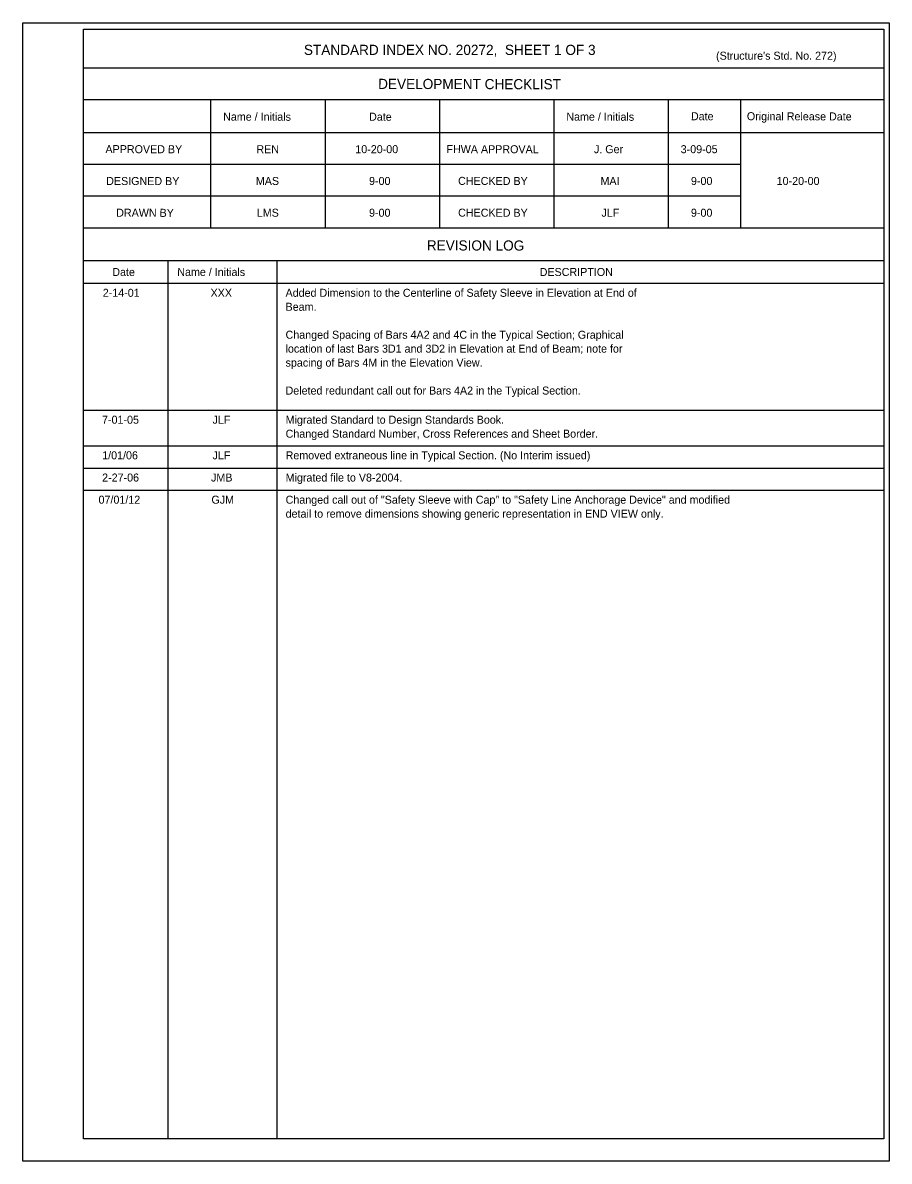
# Model space of a CAD drawing. Extents: x 120696.7 to 120732.7, y 120669.5 to 120684.8.
# Drawn here: x 120721.79 to 120732.7, y 120669.49 to 120683.83 of the extents above; entities that cross this region are included whole.
import ezdxf

# ---------------------------------------------------------------- set-up
doc = ezdxf.new("R2010")
doc.units = 0
for name, color, linetype in [('Border', 7, 'Continuous'), ('Dimension', 7, 'Continuous'), ('PlotBorder_dp', 7, 'Continuous'), ('TextStructures', 7, 'Continuous')]:
    doc.layers.add(name, color=color, linetype=linetype)

msp = doc.modelspace()

# ---------------------------------------------------------------- linework, layer by layer
at = {"layer": 'Border'}
for p, q in [((120732.633, 120683.255), (120722.559, 120683.255)), ((120732.633, 120682.855), (120722.559, 120682.855)), ((120724.159, 120682.855), (120724.159, 120681.242)), ((120725.599, 120682.855), (120725.599, 120681.242)), ((120727.039, 120682.855), (120727.039, 120681.242)), ((120728.479, 120682.855), (120728.479, 120681.242)), ((120729.919, 120682.855), (120729.919, 120681.242)), ((120730.827, 120682.855), (120730.827, 120681.242)), ((120732.633, 120682.442), (120722.559, 120682.442)), ((120730.827, 120682.042), (120722.559, 120682.042)), ((120730.827, 120681.642), (120722.559, 120681.642)), ((120732.633, 120681.242), (120722.559, 120681.242)), ((120732.633, 120680.828), (120722.559, 120680.828)), ((120723.62, 120680.828), (120723.62, 120669.774)), ((120724.991, 120680.828), (120724.991, 120669.774)), ((120732.633, 120680.546), (120722.559, 120680.546))]:
    msp.add_line(p, q, dxfattribs=at)
msp.add_lwpolyline([(120722.56, 120683.746), (120732.633, 120683.746), (120732.633, 120669.774), (120722.56, 120669.774)], close=True, dxfattribs=at)
at = {"layer": 'Dimension'}
for p, q in [((120722.56, 120678.948), (120732.633, 120678.948)), ((120722.56, 120678.5), (120732.633, 120678.5)), ((120722.56, 120678.22), (120732.633, 120678.22)), ((120722.56, 120677.941), (120732.633, 120677.941))]:
    msp.add_line(p, q, dxfattribs=at)
at = {"layer": 'PlotBorder_dp'}
msp.add_line((120721.794, 120669.494), (120721.794, 120669.494), dxfattribs=at)
msp.add_lwpolyline([(120721.794, 120683.827), (120732.701, 120683.827), (120732.701, 120669.494), (120721.794, 120669.494)], close=True, dxfattribs=at)

# ---------------------------------------------------------------- texts
at = {"layer": 'TextStructures'}
for s, height, p in [('STANDARD INDEX NO. 20272,  SHEET 1 OF 3', 0.128, (120725.333, 120683.422)), ("(Structure's Std. No. 272)", 0.1008, (120730.521, 120683.362)), ('REN', 0.1008, (120724.735, 120682.185)), ('10-20-00', 0.1008, (120725.98, 120682.185)), ('J. Ger', 0.1008, (120728.984, 120682.185)), ('3-09-05', 0.1008, (120730.076, 120682.185)), ('MAS', 0.1008, (120724.728, 120681.785)), ('9-00', 0.1008, (120726.153, 120681.785)), ('MAI', 0.1008, (120729.066, 120681.785)), ('9-00', 0.1008, (120730.205, 120681.785)), ('10-20-00', 0.1008, (120731.284, 120681.785)), ('LMS', 0.1008, (120724.74, 120681.385)), ('9-00', 0.1008, (120726.153, 120681.385)), ('JLF', 0.1008, (120729.079, 120681.385)), ('9-00', 0.1008, (120730.205, 120681.385)), ('DESCRIPTION', 0.1008, (120728.301, 120680.639)), ('2-14-01', 0.1008, (120722.801, 120680.377)), ('XXX', 0.1008, (120724.158, 120680.377)), ('Added Dimension to the Centerline of Safety Sleeve in Elevation at End of ', 0.1008, (120725.102, 120680.377)), ('Beam.', 0.1008, (120725.102, 120680.201)), ('Changed Spacing of Bars 4A2 and 4C in the Typical Section; Graphical', 0.1008, (120725.102, 120679.849)), ('location of last Bars 3D1 and 3D2 in Elevation at End of Beam; note for', 0.1008, (120725.102, 120679.674)), ('spacing of Bars 4M in the Elevation View.', 0.1008, (120725.102, 120679.498)), ('Deleted redundant call out for Bars 4A2 in the Typical Section.', 0.1008, (120725.102, 120679.146)), ('7-01-05', 0.1008, (120722.792, 120678.779)), ('JLF', 0.1008, (120724.183, 120678.779)), ('Migrated Standard to Design Standards Book.', 0.1008, (120725.103, 120678.779)), ('Changed Standard Number, Cross References and Sheet Border.', 0.1008, (120725.103, 120678.603)), ('1/01/06', 0.1008, (120722.794, 120678.331)), ('JLF', 0.1008, (120724.183, 120678.331)), ('Removed extraneous line in Typical Section. (No Interim issued)', 0.1008, (120725.103, 120678.331)), ('2-27-06', 0.1008, (120722.793, 120678.051)), ('JMB', 0.1008, (120724.164, 120678.051)), ('Migrated file to V8-2004.', 0.1008, (120725.103, 120678.051)), ('07/01/12', 0.1008, (120722.748, 120677.772)), ('GJM', 0.1008, (120724.169, 120677.772)), ('Changed call out of "Safety Sleeve with Cap" to "Safety Line Anchorage Device" and modified', 0.1008, (120725.103, 120677.772)), ('detail to remove dimensions showing generic representation in END VIEW only.', 0.1008, (120725.103, 120677.596))]:
    msp.add_text(s, height=height, dxfattribs=at).set_placement(p)
for s, height, p in [('DEVELOPMENT CHECKLIST', 0.128, (120726.267, 120682.994)), ('Name / Initials', 0.1008, (120724.316, 120682.595)), ('Name / Initials', 0.1008, (120728.636, 120682.595)), ('Date', 0.1008, (120730.205, 120682.6)), ('Original Release Date', 0.1008, (120730.909, 120682.6)), ('Date', 0.1008, (120726.153, 120682.594)), ('APPROVED BY', 0.1008, (120722.835, 120682.186)), ('FHWA APPROVAL', 0.1008, (120727.127, 120682.186)), ('DESIGNED BY', 0.1008, (120722.844, 120681.785)), ('CHECKED BY', 0.1008, (120727.274, 120681.786)), ('DRAWN BY', 0.1008, (120722.97, 120681.385)), ('CHECKED BY', 0.1008, (120727.274, 120681.386)), ('REVISION LOG', 0.128, (120726.88, 120680.961)), ('Date', 0.1008, (120722.921, 120680.639)), ('Name / Initials', 0.1008, (120723.739, 120680.64))]:
    msp.add_text(s, height=height, rotation=359.8756, dxfattribs=at).set_placement(p)

doc.saveas('drawing.dxf')
